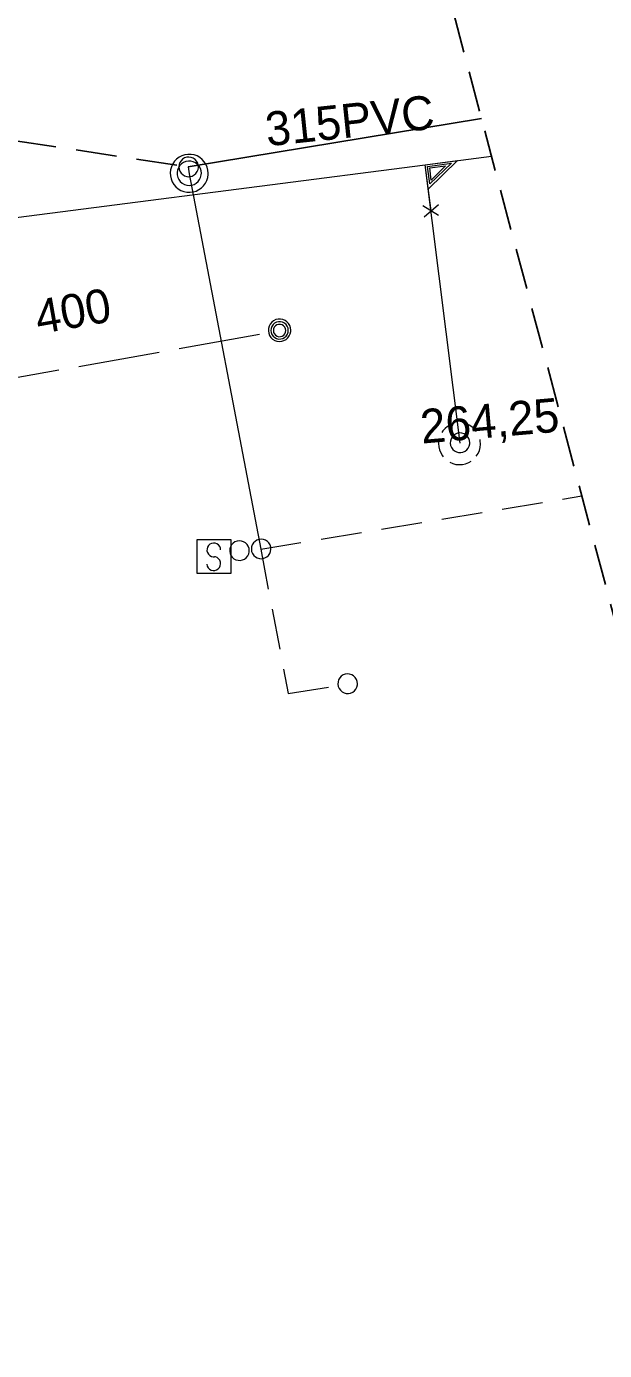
# Model space of a CAD drawing. Extents: x -732074 to -731966, y -1048695 to -1047982.
# Drawn here: x -732052.65 to -732039.05, y -1048415.55 to -1048384.41 of the extents above; entities that cross this region are included whole.
import ezdxf

# ---------------------------------------------------------------- set-up
doc = ezdxf.new("R2010")
doc.units = 0
doc.header["$LTSCALE"] = 0.32
doc.linetypes.add('LONG_DASHED', pattern=[7.5, 6, -1.5])
doc.linetypes.add('MEDIUM_DASHED', pattern=[4.5, 3, -1.5])
doc.layers.add('1', color=7, linetype='Continuous')
for name, color, linetype, lineweight in [('18', 7, 'Continuous', 13), ('20', 7, 'Continuous', 13), ('49', 7, 'Continuous', 13), ('63', 7, 'MEDIUM_DASHED', 25), ('8', 7, 'Continuous', 13)]:
    doc.layers.add(name, color=color, linetype=linetype, lineweight=lineweight)

msp = doc.modelspace()

# ---------------------------------------------------------------- linework, layer by layer
at = {"layer": '18'}
for p, q in [((-732042.954, -1048388.852), (-732043.32, -1048388.628)), ((-732043.29, -1048388.883), (-732042.954, -1048388.594))]:
    msp.add_line(p, q, dxfattribs=at)
for points in [[(-732043.129, -1048388.744), (-732043.269, -1048387.658), (-732042.505, -1048387.56), (-732043.195, -1048388.232)], [(-732043.161, -1048388.107), (-732043.214, -1048387.696), (-732042.652, -1048387.623), (-732043.16, -1048388.109)], [(-732042.602, -1048393.747), (-732042.673, -1048393.775), (-732042.74, -1048393.814), (-732042.8, -1048393.862), (-732042.851, -1048393.919), (-732042.875, -1048393.953)], [(-732042.061, -1048393.93), (-732042.111, -1048393.872), (-732042.169, -1048393.822), (-732042.234, -1048393.781), (-732042.305, -1048393.752), (-732042.354, -1048393.738)], [(-732042.947, -1048394.139), (-732042.953, -1048394.216), (-732042.948, -1048394.293), (-732042.931, -1048394.368), (-732042.902, -1048394.439), (-732042.862, -1048394.505), (-732042.846, -1048394.527)], [(-732042.066, -1048394.516), (-732042.025, -1048394.451), (-732041.994, -1048394.381), (-732041.975, -1048394.306), (-732041.967, -1048394.23), (-732041.972, -1048394.153), (-732041.978, -1048394.118)], [(-732042.689, -1048394.656), (-732042.619, -1048394.687), (-732042.544, -1048394.706), (-732042.468, -1048394.713), (-732042.391, -1048394.708), (-732042.316, -1048394.691), (-732042.244, -1048394.663), (-732042.184, -1048394.628)]]:
    msp.add_lwpolyline(points, dxfattribs=at)
for points in [[(-732043.125, -1048388.019), (-732043.162, -1048387.729), (-732042.793, -1048387.682)], [(-732046.43, -1048391.551), (-732046.436, -1048391.495), (-732046.453, -1048391.442), (-732046.482, -1048391.393), (-732046.52, -1048391.352), (-732046.566, -1048391.32), (-732046.618, -1048391.298), (-732046.673, -1048391.287), (-732046.729, -1048391.289), (-732046.784, -1048391.302), (-732046.835, -1048391.327), (-732046.879, -1048391.362), (-732046.915, -1048391.405), (-732046.94, -1048391.455), (-732046.955, -1048391.51), (-732046.958, -1048391.566), (-732046.949, -1048391.621), (-732046.928, -1048391.674), (-732046.897, -1048391.72), (-732046.857, -1048391.759), (-732046.809, -1048391.789), (-732046.756, -1048391.808), (-732046.7, -1048391.815), (-732046.644, -1048391.811), (-732046.59, -1048391.794), (-732046.541, -1048391.767), (-732046.499, -1048391.729), (-732046.466, -1048391.684), (-732046.443, -1048391.633), (-732046.431, -1048391.578)], [(-732046.489, -1048391.554), (-732046.495, -1048391.505), (-732046.513, -1048391.459), (-732046.541, -1048391.418), (-732046.578, -1048391.385), (-732046.622, -1048391.363), (-732046.67, -1048391.351), (-732046.719, -1048391.351), (-732046.767, -1048391.363), (-732046.811, -1048391.386), (-732046.848, -1048391.419), (-732046.876, -1048391.46), (-732046.893, -1048391.507), (-732046.899, -1048391.556), (-732046.892, -1048391.605), (-732046.874, -1048391.651), (-732046.846, -1048391.691), (-732046.809, -1048391.724), (-732046.765, -1048391.746), (-732046.716, -1048391.758), (-732046.667, -1048391.757), (-732046.619, -1048391.745), (-732046.576, -1048391.721), (-732046.539, -1048391.688), (-732046.511, -1048391.647), (-732046.495, -1048391.6)], [(-732046.548, -1048391.558), (-732046.554, -1048391.516), (-732046.571, -1048391.478), (-732046.599, -1048391.447), (-732046.634, -1048391.424), (-732046.674, -1048391.413), (-732046.716, -1048391.413), (-732046.756, -1048391.425), (-732046.791, -1048391.448), (-732046.818, -1048391.48), (-732046.835, -1048391.518), (-732046.84, -1048391.559), (-732046.834, -1048391.601), (-732046.816, -1048391.638), (-732046.788, -1048391.67), (-732046.752, -1048391.692), (-732046.712, -1048391.703), (-732046.67, -1048391.702), (-732046.63, -1048391.689), (-732046.596, -1048391.666), (-732046.569, -1048391.633), (-732046.553, -1048391.595)], [(-732042.218, -1048394.199), (-732042.224, -1048394.147), (-732042.242, -1048394.097), (-732042.27, -1048394.053), (-732042.308, -1048394.016), (-732042.353, -1048393.989), (-732042.403, -1048393.973), (-732042.455, -1048393.968), (-732042.507, -1048393.975), (-732042.556, -1048393.994), (-732042.6, -1048394.024), (-732042.635, -1048394.063), (-732042.661, -1048394.108), (-732042.676, -1048394.159), (-732042.679, -1048394.211), (-732042.671, -1048394.263), (-732042.65, -1048394.311), (-732042.62, -1048394.354), (-732042.58, -1048394.389), (-732042.534, -1048394.413), (-732042.483, -1048394.427), (-732042.431, -1048394.429), (-732042.379, -1048394.419), (-732042.331, -1048394.397), (-732042.289, -1048394.365), (-732042.256, -1048394.325), (-732042.232, -1048394.278), (-732042.22, -1048394.227)]]:
    msp.add_lwpolyline(points, close=True, dxfattribs=at)
at = {"layer": '20', "linetype": 'LONG_DASHED'}
msp.add_line((-732053.78, -1048392.82), (-732046.694, -1048391.564), dxfattribs=at)
msp.add_line((-732053.78, -1048392.82), (-732046.694, -1048391.564), dxfattribs=at)
at = {"layer": '20'}
msp.add_lwpolyline([(-732058.87, -1048389.67), (-732043.269, -1048387.661), (-732041.707, -1048387.459)], dxfattribs=at)
msp.add_lwpolyline([(-732058.87, -1048389.67), (-732043.269, -1048387.661), (-732041.707, -1048387.459)], dxfattribs=at)
at = {"layer": '49'}
msp.add_line((-732042.449, -1048394.21), (-732043.269, -1048387.661), dxfattribs=at)
msp.add_line((-732042.449, -1048394.21), (-732043.269, -1048387.661), dxfattribs=at)
at = {"layer": '63'}
msp.add_lwpolyline([(-731986.533, -1048110.659), (-732043.346, -1048381.295), (-732020.748, -1048466.307), (-731967.071, -1048608.112)], dxfattribs=at)
at = {"layer": '8', "lineweight": 25}
msp.add_line((-732048.844, -1048387.71), (-732041.943, -1048386.572), dxfattribs=at)
at = {"layer": '8', "linetype": 'MEDIUM_DASHED', "lineweight": 25}
msp.add_line((-732054.329, -1048386.88), (-732048.844, -1048387.71), dxfattribs=at)
at = {"layer": '8', "linetype": 'MEDIUM_DASHED'}
msp.add_line((-732047.138, -1048396.699), (-732039.584, -1048395.449), dxfattribs=at)
at = {"layer": '8'}
for points in [[(-732048.372, -1048387.859), (-732048.379, -1048387.786), (-732048.397, -1048387.715), (-732048.426, -1048387.648), (-732048.465, -1048387.587), (-732048.514, -1048387.532), (-732048.571, -1048387.487), (-732048.636, -1048387.452), (-732048.705, -1048387.427), (-732048.777, -1048387.414), (-732048.85, -1048387.413), (-732048.923, -1048387.424), (-732048.992, -1048387.447), (-732049.056, -1048387.48), (-732049.115, -1048387.524), (-732049.166, -1048387.577), (-732049.208, -1048387.637), (-732049.239, -1048387.704), (-732049.259, -1048387.774), (-732049.267, -1048387.847), (-732049.262, -1048387.92), (-732049.247, -1048387.991), (-732049.22, -1048388.059), (-732049.181, -1048388.122), (-732049.134, -1048388.177), (-732049.078, -1048388.224), (-732049.014, -1048388.261), (-732048.946, -1048388.288), (-732048.875, -1048388.303), (-732048.801, -1048388.306), (-732048.728, -1048388.297), (-732048.659, -1048388.276), (-732048.593, -1048388.244), (-732048.532, -1048388.202), (-732048.48, -1048388.151), (-732048.438, -1048388.091), (-732048.404, -1048388.026), (-732048.384, -1048387.956), (-732048.374, -1048387.884)], [(-732048.534, -1048387.859), (-732048.539, -1048387.801), (-732048.558, -1048387.745), (-732048.585, -1048387.694), (-732048.625, -1048387.65), (-732048.671, -1048387.614), (-732048.723, -1048387.589), (-732048.781, -1048387.575), (-732048.84, -1048387.573), (-732048.897, -1048387.583), (-732048.951, -1048387.605), (-732049, -1048387.637), (-732049.041, -1048387.678), (-732049.073, -1048387.727), (-732049.095, -1048387.782), (-732049.105, -1048387.839), (-732049.103, -1048387.898), (-732049.09, -1048387.955), (-732049.065, -1048388.008), (-732049.029, -1048388.054), (-732048.985, -1048388.093), (-732048.933, -1048388.121), (-732048.877, -1048388.139), (-732048.82, -1048388.145), (-732048.762, -1048388.139), (-732048.706, -1048388.122), (-732048.654, -1048388.093), (-732048.61, -1048388.054), (-732048.576, -1048388.008), (-732048.551, -1048387.955), (-732048.536, -1048387.898)], [(-732048.799, -1048387.936), (-732048.748, -1048387.923), (-732048.701, -1048387.897), (-732048.662, -1048387.863), (-732048.631, -1048387.82), (-732048.611, -1048387.771), (-732048.603, -1048387.72), (-732048.606, -1048387.667), (-732048.62, -1048387.617), (-732048.646, -1048387.571), (-732048.683, -1048387.532), (-732048.726, -1048387.504), (-732048.775, -1048387.485), (-732048.828, -1048387.477), (-732048.879, -1048387.482), (-732048.93, -1048387.498), (-732048.974, -1048387.526), (-732049.012, -1048387.562), (-732049.041, -1048387.607), (-732049.057, -1048387.656), (-732049.064, -1048387.708), (-732049.058, -1048387.76), (-732049.04, -1048387.81), (-732049.011, -1048387.854), (-732048.973, -1048387.891), (-732048.929, -1048387.918), (-732048.879, -1048387.934), (-732048.827, -1048387.939)], [(-732048.63, -1048396.475), (-732047.841, -1048396.475), (-732047.841, -1048397.275), (-732048.63, -1048397.275)], [(-732047.406, -1048396.736), (-732047.412, -1048396.684), (-732047.429, -1048396.634), (-732047.458, -1048396.59), (-732047.496, -1048396.553), (-732047.541, -1048396.526), (-732047.591, -1048396.51), (-732047.643, -1048396.505), (-732047.695, -1048396.512), (-732047.744, -1048396.531), (-732047.788, -1048396.561), (-732047.823, -1048396.6), (-732047.849, -1048396.645), (-732047.864, -1048396.696), (-732047.867, -1048396.748), (-732047.858, -1048396.8), (-732047.838, -1048396.848), (-732047.808, -1048396.891), (-732047.768, -1048396.926), (-732047.722, -1048396.95), (-732047.671, -1048396.964), (-732047.619, -1048396.966), (-732047.567, -1048396.956), (-732047.519, -1048396.934), (-732047.477, -1048396.902), (-732047.444, -1048396.862), (-732047.42, -1048396.815), (-732047.407, -1048396.764)], [(-732047.088, -1048396.924), (-732047.037, -1048396.909), (-732046.991, -1048396.883), (-732046.953, -1048396.848), (-732046.923, -1048396.804), (-732046.904, -1048396.755), (-732046.897, -1048396.703), (-732046.901, -1048396.651), (-732046.916, -1048396.601), (-732046.944, -1048396.556), (-732046.981, -1048396.518), (-732047.025, -1048396.49), (-732047.074, -1048396.472), (-732047.127, -1048396.466), (-732047.178, -1048396.472), (-732047.228, -1048396.489), (-732047.272, -1048396.518), (-732047.309, -1048396.555), (-732047.337, -1048396.6), (-732047.353, -1048396.65), (-732047.358, -1048396.702), (-732047.351, -1048396.754), (-732047.332, -1048396.803), (-732047.302, -1048396.847), (-732047.263, -1048396.883), (-732047.218, -1048396.908), (-732047.168, -1048396.924), (-732047.115, -1048396.927)], [(-732044.86, -1048399.866), (-732044.867, -1048399.814), (-732044.884, -1048399.764), (-732044.913, -1048399.72), (-732044.951, -1048399.683), (-732044.995, -1048399.656), (-732045.046, -1048399.64), (-732045.098, -1048399.635), (-732045.149, -1048399.642), (-732045.198, -1048399.661), (-732045.242, -1048399.691), (-732045.277, -1048399.73), (-732045.304, -1048399.775), (-732045.318, -1048399.826), (-732045.321, -1048399.878), (-732045.313, -1048399.93), (-732045.293, -1048399.978), (-732045.262, -1048400.021), (-732045.223, -1048400.056), (-732045.176, -1048400.08), (-732045.125, -1048400.094), (-732045.073, -1048400.096), (-732045.022, -1048400.086), (-732044.973, -1048400.064), (-732044.931, -1048400.032), (-732044.899, -1048399.992), (-732044.875, -1048399.945), (-732044.862, -1048399.894)]]:
    msp.add_lwpolyline(points, close=True, dxfattribs=at)
for points in [[(-732048.844, -1048387.71), (-732048.82, -1048387.87), (-732047.138, -1048396.699)], [(-732048.081, -1048396.721), (-732048.087, -1048396.678), (-732048.103, -1048396.637), (-732048.13, -1048396.603), (-732048.167, -1048396.577), (-732048.208, -1048396.562), (-732048.251, -1048396.559), (-732048.294, -1048396.567), (-732048.333, -1048396.587), (-732048.366, -1048396.616), (-732048.389, -1048396.654), (-732048.401, -1048396.696), (-732048.402, -1048396.739), (-732048.39, -1048396.782), (-732048.368, -1048396.819), (-732048.336, -1048396.85), (-732048.298, -1048396.87), (-732048.255, -1048396.879), (-732048.228, -1048396.879)], [(-732048.404, -1048397.058), (-732048.394, -1048397.101), (-732048.372, -1048397.14), (-732048.341, -1048397.171), (-732048.303, -1048397.192), (-732048.26, -1048397.203), (-732048.216, -1048397.201), (-732048.174, -1048397.188), (-732048.137, -1048397.164), (-732048.108, -1048397.131), (-732048.089, -1048397.091), (-732048.081, -1048397.048), (-732048.085, -1048397.004), (-732048.101, -1048396.963), (-732048.127, -1048396.928), (-732048.162, -1048396.901), (-732048.203, -1048396.884), (-732048.228, -1048396.879)]]:
    msp.add_lwpolyline(points, dxfattribs=at)
at = {"layer": '8', "linetype": 'MEDIUM_DASHED'}
msp.add_lwpolyline([(-732047.138, -1048396.699), (-732046.491, -1048400.098), (-732045.092, -1048399.877)], dxfattribs=at)

# ---------------------------------------------------------------- texts
at = {"layer": '1'}
for s, rotation, p in [('315PVC', 6, (-732046.984, -1048387.224)), ('400 ', 10, (-732052.366, -1048391.646)), ('264,25', 5, (-732043.347, -1048394.219))]:
    msp.add_text(s, height=0.8, rotation=rotation, dxfattribs=at).set_placement(p)

doc.saveas('drawing.dxf')
